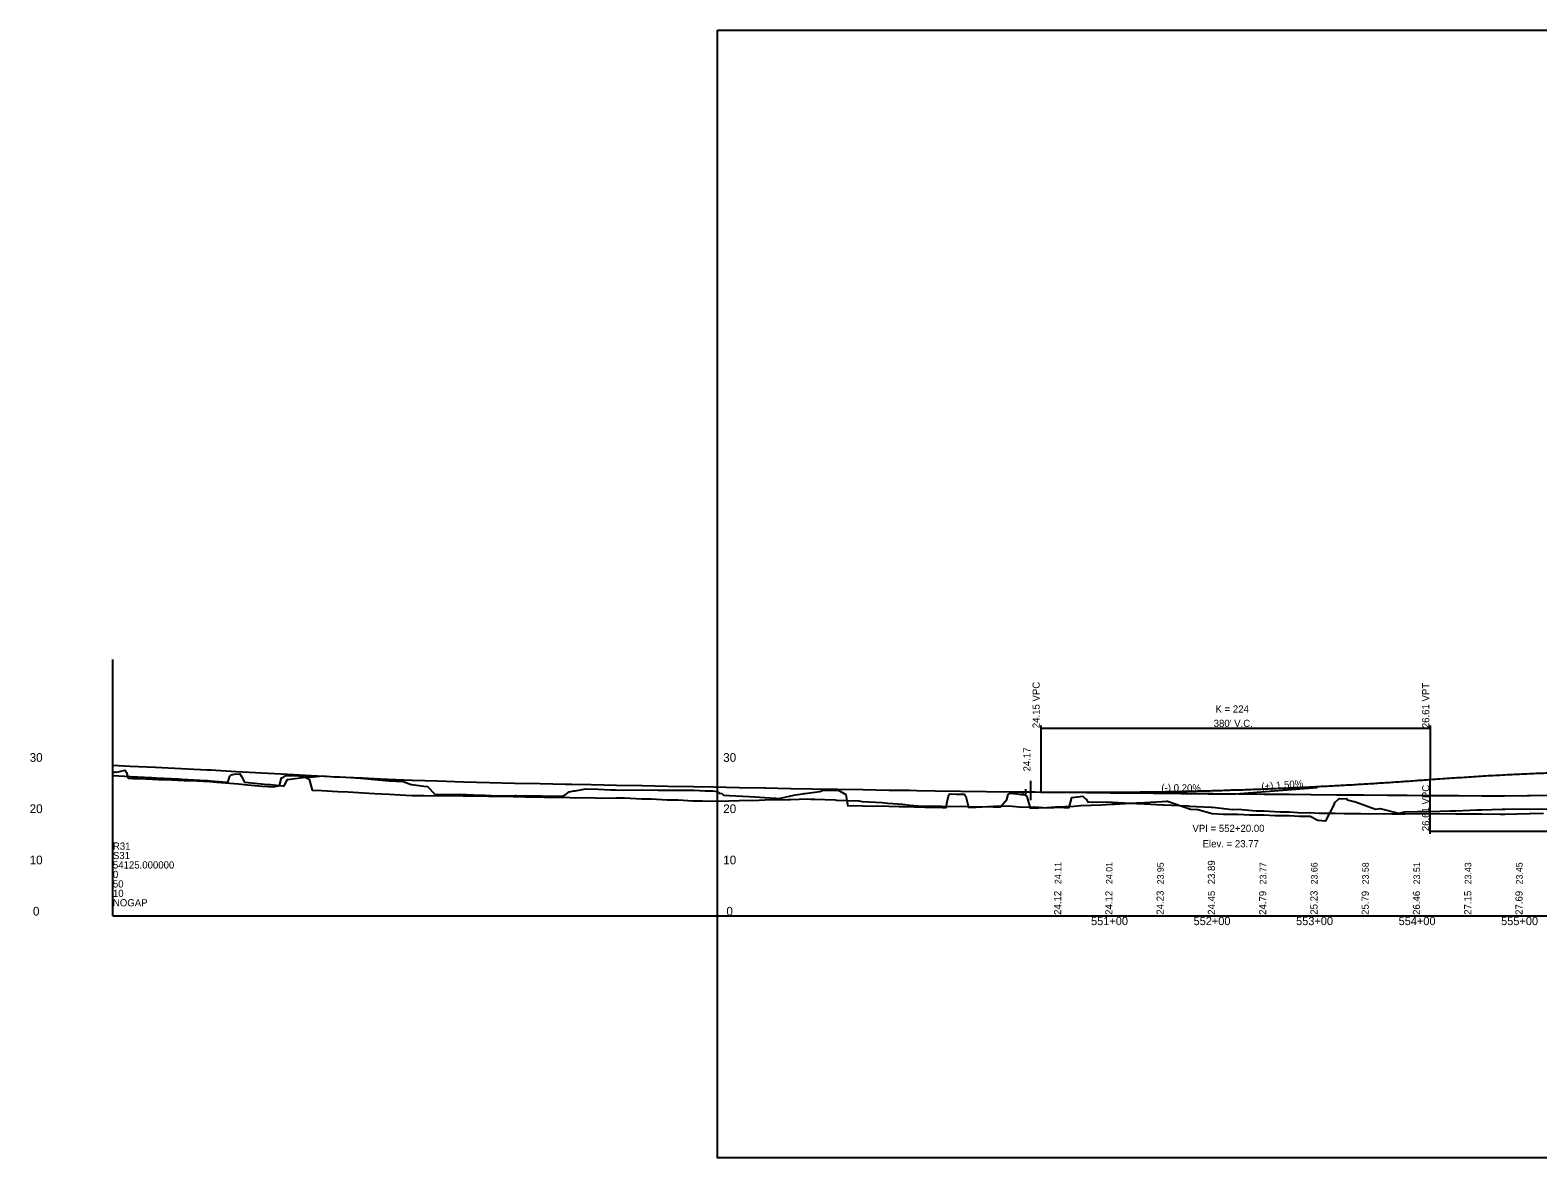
# Model space of a CAD drawing. Extents: x 2651734 to 2654815, y 758274 to 759374.
# Drawn here: x 2651734 to 2653205, y 758274 to 759374 of the extents above; entities that cross this region are included whole.
import ezdxf

# ---------------------------------------------------------------- set-up
doc = ezdxf.new("R2010")
doc.units = 0
for name, color, linetype in [('BR_CONCRETE', 7, 'Continuous'), ('BR_EXIST_GROUND_RT', 7, 'Continuous'), ('RD_EX_H2O_txCode', 7, 'Continuous'), ('RD_PD_CstnLmt', 7, 'Continuous'), ('RD_PD_CstnLmt_TX', 7, 'Continuous'), ('RD_PD_DR_ErosCtrl', 7, 'Continuous'), ('RD_PD_Final_TrvlWay', 7, 'Continuous'), ('RD_PD_PaveShd', 7, 'Continuous'), ('RD_PD_RW_TX', 7, 'Continuous'), ('RD_SHT_IplotShp', 7, 'Continuous'), ('RD_SHT_ShtClip', 7, 'Continuous'), ('RD_Sketch8', 7, 'Continuous')]:
    doc.layers.add(name, color=color, linetype=linetype)

msp = doc.modelspace()

# ---------------------------------------------------------------- linework, layer by layer
at = {"layer": 'BR_CONCRETE'}
msp.add_lwpolyline([(2651814.9, 758656.9), (2651831.6, 758656.1), (2651856.6, 758654.9), (2651881.6, 758653.7), (2651906.6, 758652.5), (2651910.3, 758652.3), (2651935.1, 758650.9), (2651960.1, 758649.5), (2651985.1, 758648.1), (2652008.2, 758646.8), (2652033.2, 758645.6), (2652058.2, 758644.5), (2652075.7, 758643.6), (2652083.2, 758643.3), (2652106.9, 758642.2), (2652131.9, 758641.5), (2652156.9, 758640.7), (2652182.1, 758640), (2652206.6, 758639.3), (2652231.5, 758638.9), (2652256.4, 758638.4), (2652262.3, 758638.3), (2652281.4, 758638), (2652306.2, 758637.5), (2652331.2, 758637.1), (2652356.2, 758636.6), (2652381.2, 758636.2), (2652401.1, 758635.9), (2652425.8, 758635.3), (2652426.2, 758635.3), (2652450.7, 758634.8), (2652451.3, 758634.8), (2652475.7, 758634.3), (2652476.4, 758634.3), (2652496.8, 758633.9), (2652521.1, 758633.5), (2652521.8, 758633.5), (2652546.3, 758633.1), (2652546.7, 758633.1), (2652571.6, 758632.7), (2652589.5, 758632.4), (2652591.8, 758632.4), (2652598.9, 758632.3), (2652616.9, 758632), (2652641.9, 758631.7), (2652666.9, 758631.3), (2652689.4, 758631), (2652714.4, 758630.8), (2652739.5, 758630.5), (2652764.6, 758630.2), (2652787.7, 758630), (2652812.7, 758629.9), (2652837.7, 758629.7), (2652862.4, 758629.6), (2652862.7, 758629.6), (2652887, 758629.4), (2652887.4, 758629.4), (2652887.8, 758629.4), (2652912.4, 758629.1), (2652912.7, 758629.1), (2652937.4, 758628.8), (2652937.7, 758628.8), (2652962.7, 758628.5), (2652983.3, 758628.3), (2652983.7, 758628.3), (2653008.3, 758628.1), (2653009.1, 758628.1), (2653033.3, 758627.9), (2653034.6, 758627.9), (2653058.3, 758627.7), (2653059.5, 758627.7), (2653075.4, 758627.6), (2653077.4, 758627.6), (2653100.4, 758627.4), (2653102.5, 758627.4), (2653125.4, 758627.2), (2653127.6, 758627.2), (2653150.4, 758627), (2653152.4, 758627), (2653172.2, 758626.9), (2653194.6, 758627.3), (2653197.2, 758627.3), (2653219.4, 758627.7)], dxfattribs=at)
at = {"layer": 'BR_EXIST_GROUND_RT'}
msp.add_lwpolyline([(2651814.9, 758649.8), (2651816.5, 758650.2), (2651817.1, 758650.3), (2651818.6, 758650.1), (2651826.6, 758651.9), (2651827.9, 758649.9), (2651828.3, 758649.8), (2651829.2, 758646.3), (2651829.7, 758644.3), (2651834.5, 758644), (2651841.4, 758644), (2651859.5, 758643.1), (2651866.2, 758643.1), (2651884.5, 758642.1), (2651891, 758642.1), (2651909.5, 758641.1), (2651916.4, 758640.5), (2651920.6, 758640.1), (2651937.4, 758638.7), (2651946.1, 758637.9), (2651960.6, 758636.6), (2651971.8, 758635.7), (2651977.4, 758637.1), (2651979.4, 758644.7), (2651981, 758644.9), (2651983.7, 758647), (2651992, 758646.8), (2652000.2, 758646.2), (2652004.5, 758644.1), (2652006.4, 758643.2), (2652009.4, 758632.7), (2652018.7, 758632.3), (2652034.3, 758631.3), (2652044.3, 758630.8), (2652059.3, 758629.9), (2652070.1, 758629.4), (2652084.2, 758628.5), (2652095.1, 758628), (2652106.4, 758627.3), (2652118.5, 758627.4), (2652131.4, 758627.1), (2652142.8, 758627.2), (2652156.4, 758626.9), (2652167.3, 758626.9), (2652181.4, 758626.6), (2652191.3, 758626.6), (2652205.4, 758626.3), (2652216.7, 758625.9), (2652230.4, 758625.9), (2652241.3, 758625.5), (2652255.4, 758625.6), (2652265.7, 758625.2), (2652280.4, 758625.4), (2652290.1, 758624.9), (2652305.6, 758625.2), (2652313.9, 758625), (2652330.6, 758624.2), (2652340, 758624), (2652355.6, 758623.2), (2652366.1, 758623), (2652380.6, 758622.3), (2652390, 758622.2), (2652400.8, 758621.7), (2652415.7, 758622), (2652425.7, 758622.4), (2652444.9, 758622.9), (2652450.7, 758623.1), (2652473.5, 758623.6), (2652475.7, 758623.6), (2652492.8, 758624), (2652495.5, 758623.9), (2652499.6, 758623.8), (2652519.3, 758623.1), (2652520.6, 758622.9), (2652542.5, 758622), (2652545.6, 758621.6), (2652565.2, 758620.6), (2652570.7, 758619.8), (2652585.1, 758619), (2652592, 758617.8), (2652604.7, 758616.9), (2652617, 758617.3), (2652629.9, 758616.6), (2652642, 758616.9), (2652655, 758616.3), (2652667, 758616.6), (2652673.5, 758616.3), (2652680.6, 758616.4), (2652687, 758623.6), (2652688.2, 758628.4), (2652690, 758629.7), (2652696.5, 758628.9), (2652701.2, 758628.2), (2652703.6, 758628.2), (2652704.1, 758627.9), (2652706.2, 758626.4), (2652709.6, 758614.9), (2652725.9, 758615.7), (2652734.3, 758616.2), (2652752.4, 758617), (2652759, 758617.5), (2652779.2, 758618.3), (2652783.7, 758618.6), (2652788.3, 758618.8), (2652791.9, 758618.8), (2652813.3, 758620.1), (2652815.7, 758620.1), (2652838.4, 758621.5), (2652842.5, 758621.8), (2652843.7, 758621.8), (2652866, 758613.9), (2652873.3, 758613.8), (2652887.1, 758609.9), (2652898.3, 758609.2), (2652912.1, 758609.2), (2652923.4, 758608.6), (2652937.1, 758608.6), (2652948.6, 758607.9), (2652962.1, 758607.9), (2652972.3, 758607.2), (2652982.8, 758607.2), (2652990.1, 758603.3), (2652998.1, 758602.6), (2653006, 758618.3), (2653006.7, 758620.6), (2653010.2, 758623.8), (2653011, 758624.3), (2653012.4, 758624.2), (2653018.1, 758624.4), (2653018.9, 758623.2), (2653025.2, 758621.4), (2653025.6, 758621.4), (2653027, 758621.3), (2653046.6, 758614.1), (2653051.1, 758614.8), (2653068.8, 758610), (2653075.1, 758611.3), (2653087.1, 758611.6), (2653099.8, 758611.7), (2653119.4, 758612.3), (2653124.8, 758612.5), (2653145.4, 758613.2), (2653149.7, 758613.3), (2653169.9, 758614), (2653172.9, 758614.1), (2653194.2, 758614.3), (2653197.9, 758614), (2653218.8, 758614.2)], dxfattribs=at)
at = {"layer": 'RD_EX_H2O_txCode'}
for q in [(2651814.9, 758759.9), (2654814.9, 758509.9), (2651814.9, 758509.9)]:
    msp.add_line((2651814.9, 758509.9), q, dxfattribs=at)
at = {"layer": 'RD_PD_DR_ErosCtrl'}
msp.add_line((2652709.9, 758630.8), (2652719.9, 758630.7), dxfattribs=at)
for points in [[(2653099.9, 758643), (2653109.3, 758643.7), (2653118.7, 758644.3), (2653128.1, 758644.9), (2653137.5, 758645.5), (2653146.9, 758646.1), (2653156.3, 758646.7), (2653165.7, 758647.2), (2653175.1, 758647.7), (2653184.5, 758648.1), (2653193.9, 758648.6), (2653203.3, 758649), (2653212.7, 758649.3), (2653222.1, 758649.7), (2653231.5, 758650), (2653240.9, 758650.3), (2653250.3, 758650.6), (2653259.7, 758650.8), (2653269.1, 758651), (2653278.5, 758651.2), (2653287.9, 758651.3), (2653297.3, 758651.4), (2653306.7, 758651.5), (2653316.1, 758651.6), (2653325.5, 758651.6), (2653334.9, 758651.6), (2653344.3, 758651.6), (2653353.7, 758651.6), (2653363.1, 758651.5), (2653372.5, 758651.4), (2653381.9, 758651.2), (2653391.3, 758651.1), (2653400.7, 758650.9), (2653410.1, 758650.7), (2653419.5, 758650.4), (2653428.9, 758650.1), (2653438.3, 758649.8), (2653447.7, 758649.5), (2653457.1, 758649.1), (2653466.5, 758648.7), (2653475.9, 758648.3), (2653485.3, 758647.9), (2653494.7, 758647.4), (2653504.1, 758646.9), (2653513.5, 758646.3), (2653522.9, 758645.8), (2653532.3, 758645.2), (2653541.7, 758644.6), (2653551.1, 758643.9), (2653560.5, 758643.2), (2653569.9, 758642.5)], [(2652719.9, 758630.7), (2652727.5, 758630.6), (2652735.1, 758630.6), (2652742.7, 758630.5), (2652750.3, 758630.5), (2652757.9, 758630.5), (2652765.5, 758630.5), (2652773.1, 758630.5), (2652780.7, 758630.5), (2652788.3, 758630.5), (2652795.9, 758630.6), (2652803.5, 758630.6), (2652811.1, 758630.7), (2652818.7, 758630.8), (2652826.3, 758630.9), (2652833.9, 758631), (2652841.5, 758631.1), (2652849.1, 758631.2), (2652856.7, 758631.4), (2652864.3, 758631.6), (2652871.9, 758631.7), (2652879.5, 758631.9), (2652887.1, 758632.1), (2652894.7, 758632.3), (2652902.3, 758632.6), (2652909.9, 758632.8), (2652917.5, 758633), (2652925.1, 758633.3), (2652932.7, 758633.6), (2652940.3, 758633.9), (2652947.9, 758634.2), (2652955.5, 758634.5), (2652963.1, 758634.8), (2652970.7, 758635.2), (2652978.3, 758635.5), (2652985.9, 758635.9), (2652993.5, 758636.3), (2653001.1, 758636.7), (2653008.7, 758637.1), (2653016.3, 758637.5), (2653023.9, 758637.9), (2653031.5, 758638.4), (2653039.1, 758638.8), (2653046.7, 758639.3), (2653054.3, 758639.8), (2653061.9, 758640.3), (2653069.5, 758640.8), (2653077.1, 758641.3), (2653084.7, 758641.9), (2653092.3, 758642.4), (2653099.9, 758643)]]:
    msp.add_spline(points, degree=3, dxfattribs=at)
at = {"layer": 'RD_PD_RW_TX'}
msp.add_lwpolyline([(2651814.9, 758647), (2651832.2, 758646), (2651852.4, 758644.9), (2651857.2, 758644.7), (2651878.9, 758643.5), (2651882.2, 758643.3), (2651905.5, 758642), (2651907.2, 758641.9), (2651910.2, 758641.7), (2651926.5, 758640.4), (2651927.1, 758640.5), (2651928.9, 758646.2), (2651929.3, 758646.5), (2651930.4, 758647.5), (2651933.6, 758648.1), (2651938.8, 758648.4), (2651940.2, 758645.9), (2651942.5, 758641.6), (2651943.6, 758640.3), (2651966.1, 758638.1), (2651968.6, 758638), (2651980.5, 758636.8), (2651982, 758636.7), (2651985.2, 758643.1), (2652005, 758645.6), (2652007.3, 758645.5), (2652007.9, 758645.5), (2652010.3, 758645.5), (2652019.6, 758646.4), (2652030.7, 758645.7), (2652035.1, 758645.5), (2652035.9, 758645.5), (2652042.2, 758645.1), (2652056.3, 758644.1), (2652084.5, 758641.7), (2652097.9, 758641), (2652105.9, 758638.1), (2652106.5, 758638), (2652118.2, 758636.4), (2652121.8, 758636), (2652128.8, 758628.8), (2652137.1, 758628.4), (2652153.4, 758628.5), (2652166.7, 758627.9), (2652178.1, 758627.8), (2652189.6, 758627.1), (2652197.2, 758627.1), (2652206.8, 758627.5), (2652208.1, 758627.4), (2652225.1, 758627.1), (2652233.1, 758627), (2652247.1, 758626.7), (2652253, 758626.7), (2652255.7, 758627.6), (2652260, 758630.8), (2652264.5, 758632), (2652265.8, 758632), (2652276.1, 758633.7), (2652288.1, 758633.5), (2652300.4, 758632.9), (2652305.1, 758632.8), (2652313.4, 758632.7), (2652331.5, 758632.9), (2652346.9, 758632.6), (2652356.5, 758632.7), (2652371.6, 758632.5), (2652381.5, 758632.6), (2652392.6, 758631.9), (2652400, 758631.8), (2652404.3, 758631.3), (2652406.4, 758629.7), (2652408.7, 758629.4), (2652410.6, 758627.8), (2652416.1, 758627.4), (2652435.6, 758626.3), (2652441.1, 758625.9), (2652460.6, 758624.8), (2652461.6, 758624.7), (2652464.8, 758624.5), (2652479.2, 758627.7), (2652489.2, 758629.3), (2652490, 758629.2), (2652504.2, 758631.2), (2652504.6, 758631.3), (2652507.7, 758632.6), (2652516.3, 758632.4), (2652523, 758632.3), (2652523.7, 758631.9), (2652529.8, 758628.4), (2652531, 758620.6), (2652531.6, 758617.4), (2652537, 758617.5), (2652556.6, 758617), (2652561.8, 758617.1), (2652581.7, 758616.5), (2652586.6, 758616.7), (2652606.7, 758616.1), (2652624.2, 758615.5), (2652627.6, 758615.7), (2652628.7, 758621.3), (2652629.8, 758626.8), (2652630.2, 758628), (2652630.8, 758628.9), (2652637.6, 758628.6), (2652645.3, 758628.6), (2652646, 758627.3), (2652646.9, 758626.4), (2652649.3, 758615.9), (2652657, 758616), (2652674.1, 758616.8), (2652680.2, 758616.8), (2652688.4, 758617.1), (2652702.4, 758615.9), (2652713.4, 758616.4), (2652726.8, 758615.3), (2652738.4, 758615.8), (2652742.4, 758615.5), (2652747.8, 758615.7), (2652750.1, 758625.5), (2652753.2, 758625.8), (2652761, 758626.6), (2652763.5, 758624.2), (2652764.5, 758623.3), (2652765.1, 758622.2), (2652765.7, 758621), (2652785.5, 758621.1), (2652789.8, 758620.8), (2652813.3, 758619.7), (2652814.6, 758619.7), (2652839, 758618.3), (2652839.6, 758618.3), (2652863.6, 758617.1), (2652864.6, 758617), (2652886.3, 758615.9), (2652887.6, 758615.8), (2652907.1, 758613.8), (2652912.6, 758613.9), (2652930, 758612.4), (2652937.7, 758612.4), (2652953.6, 758611.3), (2652962.7, 758611.3), (2652974.7, 758610.5), (2652982.2, 758610.6), (2652991.4, 758610.2), (2653007.2, 758610.2), (2653015.8, 758609.8), (2653032.2, 758609.9), (2653040.2, 758609.6), (2653057.2, 758609.7), (2653062.4, 758609.5), (2653074.9, 758609.6), (2653081.2, 758609.8), (2653099.9, 758609.5), (2653105.5, 758609.7), (2653124.9, 758609.4), (2653130, 758609.5), (2653149.9, 758609.3), (2653168.1, 758609.1), (2653172.5, 758609.1), (2653196.7, 758609.8), (2653197.3, 758609.8), (2653210.3, 758610)], dxfattribs=at)
at = {"layer": 'RD_SHT_IplotShp'}
for p in [(2652829.9, 758629.6), (2652989.7, 758634.7)]:
    msp.add_line(p, (2652909.9, 758628.8), dxfattribs=at)
at = {"layer": 'RD_SHT_ShtClip'}
for p, q in [((2652709.9, 758641.7), (2652709.9, 758622.8)), ((2652704.9, 758633.6), (2652704.9, 758628.4)), ((2652704.9, 758630.9), (2652709.9, 758630.8))]:
    msp.add_line(p, q, dxfattribs=at)
msp.add_lwpolyline([(2652404.5, 759373.9), (2654204.5, 759373.9), (2654204.5, 758273.9), (2652404.5, 758273.9)], close=True, dxfattribs=at)
at = {"layer": 'RD_Sketch8'}
for p, q in [((2652719.9, 758695.5), (2652719.9, 758630.7)), ((2653099.9, 758695.5), (2653099.9, 758643)), ((2652719.9, 758693), (2653099.9, 758693)), ((2653099.9, 758590), (2653099.9, 758643)), ((2653099.9, 758592.5), (2653569.9, 758592.5))]:
    msp.add_line(p, q, dxfattribs=at)

# ---------------------------------------------------------------- texts
at = {"layer": 'RD_EX_H2O_txCode'}
for s, p in [('R31', (2651814.9, 758574.5)), ('S31', (2651814.9, 758565.3)), ('54125.000000', (2651814.9, 758556.1)), ('0', (2651814.9, 758546.9)), ('50', (2651814.9, 758537.6)), ('10', (2651814.9, 758528.4)), ('NOGAP', (2651814.9, 758519.2))]:
    msp.add_text(s, height=7, dxfattribs=at).set_placement(p)
at = {"layer": 'RD_PD_CstnLmt'}
for s, p in [('551+00', (2652769, 758500.9)), ('552+00', (2652869, 758500.9)), ('553+00', (2652969, 758500.9)), ('554+00', (2653069, 758500.9)), ('555+00', (2653169, 758500.9))]:
    msp.add_text(s, height=8, dxfattribs=at).set_placement(p)
at = {"layer": 'RD_PD_CstnLmt_TX'}
for s, p in [('30', (2651733.7, 758660.2)), ('30', (2652410.2, 758660.2)), ('20', (2651733.7, 758610.2)), ('20', (2652410.2, 758610.2)), ('10', (2651733.7, 758560.2)), ('10', (2652410.2, 758560.2)), ('0', (2651736.9, 758510.2)), ('0', (2652413.3, 758510.2))]:
    msp.add_text(s, height=8.5, dxfattribs=at).set_placement(p)
at = {"layer": 'RD_PD_Final_TrvlWay'}
for s, height, p in [('24.15 VPC', 7, (2652718.9, 758693)), ('26.61 VPT', 7, (2653098.9, 758693)), ('26.61 VPC', 7, (2653098.9, 758592.5)), ('23.89', 7, (2652889.9, 758540.7)), ('24.11', 6.4, (2652739.9, 758541)), ('24.01', 6.4, (2652789.9, 758541)), ('23.95', 6.4, (2652839.9, 758540.7)), ('23.77', 6.4, (2652939.9, 758540.7)), ('23.66', 6.4, (2652989.9, 758540.7)), ('23.58', 6.4, (2653039.9, 758540.7)), ('23.51', 6.4, (2653089.9, 758540.7)), ('23.43', 6.4, (2653139.9, 758540.7)), ('23.45', 6.4, (2653189.9, 758540.7)), ('24.12', 7, (2652739.9, 758510.9)), ('24.12', 7, (2652789.9, 758510.9)), ('24.23', 7, (2652839.9, 758511.1)), ('24.45', 7, (2652889.9, 758511)), ('24.79', 7, (2652939.9, 758510.9)), ('25.23', 7, (2652989.9, 758511.1)), ('25.79', 7, (2653039.9, 758510.9)), ('26.46', 7, (2653089.9, 758510.9)), ('27.15', 7, (2653139.9, 758511)), ('27.69', 7, (2653189.9, 758510.9))]:
    msp.add_text(s, height=height, rotation=90, dxfattribs=at).set_placement(p)
at = {"layer": 'RD_PD_PaveShd'}
msp.add_text('24.17', height=7, rotation=90, dxfattribs=at).set_placement((2652709.9, 758650.8))
for s, p in [('VPI = 552+20.00', (2652867.9, 758591.8)), ('Elev. = 23.77', (2652877.8, 758576.8))]:
    msp.add_text(s, height=7, dxfattribs=at).set_placement(p)
at = {"layer": 'RD_SHT_IplotShp'}
for s, rotation, p in [('(-) 0.20%', 359.4156, (2652837.6, 758631.5)), ('(+) 1.50%', 4.2749, (2652935.4, 758632.7))]:
    msp.add_text(s, height=7, rotation=rotation, dxfattribs=at).set_placement(p)
at = {"layer": 'RD_SHT_ShtClip'}
msp.add_text('-0.2040', height=2, dxfattribs=at).set_placement((2652695.4, 758628.7))
at = {"layer": 'RD_Sketch8'}
for s, p in [('K = 224', (2652890.4, 758708.2)), ("380' V.C.", (2652888.6, 758694.2))]:
    msp.add_text(s, height=7, dxfattribs=at).set_placement(p)

doc.saveas('drawing.dxf')
